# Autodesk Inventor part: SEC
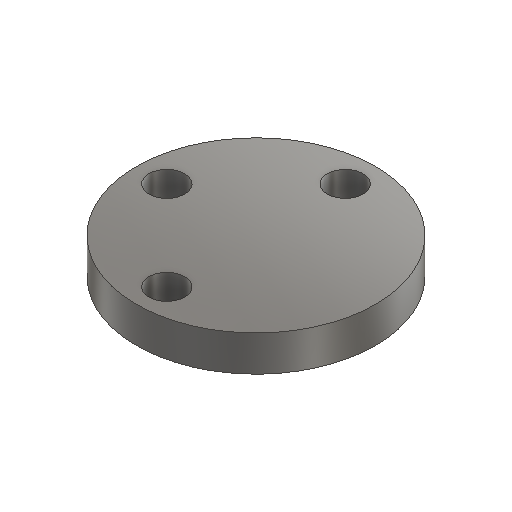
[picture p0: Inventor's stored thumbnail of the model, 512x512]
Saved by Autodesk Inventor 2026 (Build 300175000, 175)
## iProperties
Created: 2015-09
Part Number: SEC
Material: Steel, Mild
Document SubType Name: Modeling
Designer: Lars Bertram Pedersen
Density: 7.85 g/cm^3
Appearance: Semi-Polished
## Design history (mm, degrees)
sketch "Sketch1"
  geometry: C1 r 33.5 at (0, 0); 1 further point
  constraints: 1 centre point, 1 coincident
  dimensions: "d0" = 67 diameter of C1
extrude "Extrusion1" new body sketch "Sketch1" distance "d1" = 10; taper "d2" = 0 deg
sketch "Sketch2"
  geometry: 2 further points
  constraints: 1 vertical alignment
  dimensions: "d3" = 25 distance of point (0, 0) point (0, 25)
hole "Hole1" sketch "Sketch2" diameter "d4" = 10; stored, may be unused: countersink angle "d8" = 90 deg, drill point angle "d10" = 118 deg; dims "d5" = 6, "d6" = 4, "d7" = 2, "d9" = 8
pattern_circular "Circular Pattern1" dims angle "d12" = 180 deg
body "Solid1"
